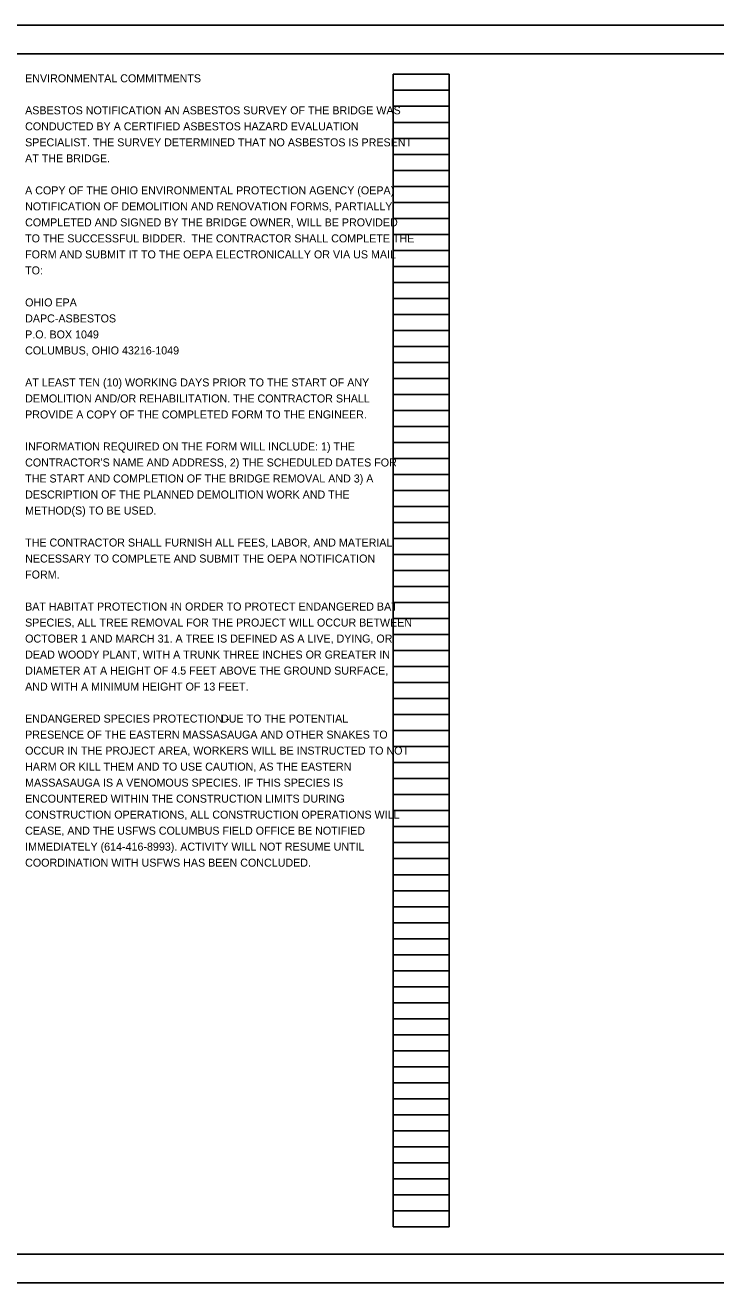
# Model space of a CAD drawing. Extents: x -8.3 to 34, y 0 to 22.
# Drawn here: x 9.82 to 21.91, y 0 to 22 of the extents above; entities that cross this region are included whole.
import ezdxf

# ---------------------------------------------------------------- set-up
doc = ezdxf.new("R2010")
doc.units = 0
for name, color, linetype in [('SH_Border', 7, 'Continuous'), ('SH_Cut_Line', 7, 'Continuous'), ('SH_Data', 7, 'Continuous'), ('SH_Text', 7, 'Continuous')]:
    doc.layers.add(name, color=color, linetype=linetype)

msp = doc.modelspace()

# ---------------------------------------------------------------- linework, layer by layer
at = {"layer": 'SH_Border'}
msp.add_lwpolyline([(1.5, 21.5), (33.5, 21.5), (33.5, 0.5), (1.5, 0.5)], close=True, dxfattribs=at)
at = {"layer": 'SH_Cut_Line'}
msp.add_lwpolyline([(0, 0), (34, 0), (34, 22), (0, 22)], close=True, dxfattribs=at)
at = {"layer": 'SH_Data'}
for p, q in [((16.26, 0.98), (16.26, 21.14)), ((16.26, 21.14), (17.24, 21.14)), ((17.24, 0.98), (17.24, 21.14)), ((16.26, 20.86), (17.24, 20.86)), ((16.26, 20.58), (17.24, 20.58)), ((16.26, 20.3), (17.24, 20.3)), ((16.26, 20.02), (17.24, 20.02)), ((16.26, 19.74), (17.24, 19.74)), ((16.26, 19.46), (17.24, 19.46)), ((16.26, 19.18), (17.24, 19.18)), ((16.26, 18.9), (17.24, 18.9)), ((16.26, 18.62), (17.24, 18.62)), ((16.26, 18.34), (17.24, 18.34)), ((16.26, 18.06), (17.24, 18.06)), ((16.26, 17.78), (17.24, 17.78)), ((16.26, 17.5), (17.24, 17.5)), ((16.26, 17.22), (17.24, 17.22)), ((16.26, 16.94), (17.24, 16.94)), ((16.26, 16.66), (17.24, 16.66)), ((16.26, 16.38), (17.24, 16.38)), ((16.26, 16.1), (17.24, 16.1)), ((16.26, 15.82), (17.24, 15.82)), ((16.26, 15.54), (17.24, 15.54)), ((16.26, 15.26), (17.24, 15.26)), ((16.26, 14.98), (17.24, 14.98)), ((16.26, 14.7), (17.24, 14.7)), ((16.26, 14.42), (17.24, 14.42)), ((16.26, 14.14), (17.24, 14.14)), ((16.26, 13.86), (17.24, 13.86)), ((16.26, 13.58), (17.24, 13.58)), ((16.26, 13.3), (17.24, 13.3)), ((16.26, 13.02), (17.24, 13.02)), ((16.26, 12.74), (17.24, 12.74)), ((16.26, 12.46), (17.24, 12.46)), ((16.26, 12.18), (17.24, 12.18)), ((16.26, 11.9), (17.24, 11.9)), ((16.26, 11.62), (17.24, 11.62)), ((16.26, 11.34), (17.24, 11.34)), ((16.26, 11.06), (17.24, 11.06)), ((16.26, 10.78), (17.24, 10.78)), ((16.26, 10.5), (17.24, 10.5)), ((16.26, 10.22), (17.24, 10.22)), ((16.26, 9.94), (17.24, 9.94)), ((16.26, 9.66), (17.24, 9.66)), ((16.26, 9.38), (17.24, 9.38)), ((16.26, 9.1), (17.24, 9.1)), ((16.26, 8.82), (17.24, 8.82)), ((16.26, 8.54), (17.24, 8.54)), ((16.26, 8.26), (17.24, 8.26)), ((16.26, 7.98), (17.24, 7.98)), ((16.26, 7.7), (17.24, 7.7)), ((16.26, 7.42), (17.24, 7.42)), ((16.26, 7.14), (17.24, 7.14)), ((16.26, 6.86), (17.24, 6.86)), ((16.26, 6.58), (17.24, 6.58)), ((16.26, 6.3), (17.24, 6.3)), ((16.26, 6.02), (17.24, 6.02)), ((16.26, 5.74), (17.24, 5.74)), ((16.26, 5.46), (17.24, 5.46)), ((16.26, 5.18), (17.24, 5.18)), ((16.26, 4.9), (17.24, 4.9)), ((16.26, 4.62), (17.24, 4.62)), ((16.26, 4.34), (17.24, 4.34)), ((16.26, 4.06), (17.24, 4.06)), ((16.26, 3.78), (17.24, 3.78)), ((16.26, 3.5), (17.24, 3.5)), ((16.26, 3.22), (17.24, 3.22)), ((16.26, 2.94), (17.24, 2.94)), ((16.26, 2.66), (17.24, 2.66)), ((16.26, 2.38), (17.24, 2.38)), ((16.26, 2.1), (17.24, 2.1)), ((16.26, 1.82), (17.24, 1.82)), ((16.26, 1.54), (17.24, 1.54)), ((16.26, 1.26), (17.24, 1.26)), ((16.26, 0.98), (17.24, 0.98))]:
    msp.add_line(p, q, dxfattribs=at)

# ---------------------------------------------------------------- texts
at = {"layer": 'SH_Text'}
for s, p in [('ENVIRONMENTAL COMMITMENTS', (9.82, 21)), ('ASBESTOS NOTIFICATION - ', (9.82, 20.44)), ('AN ASBESTOS SURVEY OF THE BRIDGE WAS ', (12.264, 20.44)), ('CONDUCTED BY A CERTIFIED ASBESTOS HAZARD EVALUATION ', (9.82, 20.16)), ('SPECIALIST. THE SURVEY DETERMINED THAT NO ASBESTOS IS PRESENT ', (9.82, 19.88)), ('AT THE BRIDGE.', (9.82, 19.6)), ('A COPY OF THE OHIO ENVIRONMENTAL PROTECTION AGENCY (OEPA) ', (9.82, 19.04)), ('NOTIFICATION OF DEMOLITION AND RENOVATION FORMS, PARTIALLY ', (9.82, 18.76)), ('COMPLETED AND SIGNED BY THE BRIDGE OWNER, WILL BE PROVIDED ', (9.82, 18.48)), ('TO THE SUCCESSFUL BIDDER.  THE CONTRACTOR SHALL COMPLETE THE ', (9.82, 18.2)), ('FORM AND SUBMIT IT TO THE OEPA ELECTRONICALLY OR VIA US MAIL ', (9.82, 17.92)), ('TO:', (9.82, 17.64)), ('OHIO EPA', (9.82, 17.08)), ('DAPC-ASBESTOS', (9.82, 16.8)), ('P.O. BOX 1049', (9.82, 16.52)), ('COLUMBUS, OHIO 43216-1049', (9.82, 16.24)), ('AT LEAST TEN (10) WORKING DAYS PRIOR TO THE START OF ANY ', (9.82, 15.68)), ('DEMOLITION AND/OR REHABILITATION. THE CONTRACTOR SHALL ', (9.82, 15.4)), ('PROVIDE A COPY OF THE COMPLETED FORM TO THE ENGINEER.', (9.82, 15.12)), ('INFORMATION REQUIRED ON THE FORM WILL INCLUDE: 1) THE ', (9.82, 14.56)), ("CONTRACTOR'S NAME AND ADDRESS, 2) THE SCHEDULED DATES FOR ", (9.82, 14.28)), ('THE START AND COMPLETION OF THE BRIDGE REMOVAL AND 3) A ', (9.82, 14)), ('DESCRIPTION OF THE PLANNED DEMOLITION WORK AND THE ', (9.82, 13.72)), ('METHOD(S) TO BE USED. ', (9.82, 13.44)), ('THE CONTRACTOR SHALL FURNISH ALL FEES, LABOR, AND MATERIAL ', (9.82, 12.88)), ('NECESSARY TO COMPLETE AND SUBMIT THE OEPA NOTIFICATION ', (9.82, 12.6)), ('FORM.', (9.82, 12.32)), ('BAT HABITAT PROTECTION - ', (9.82, 11.76)), ('IN ORDER TO PROTECT ENDANGERED BAT ', (12.379, 11.76)), ('SPECIES, ALL TREE REMOVAL FOR THE PROJECT WILL OCCUR BETWEEN ', (9.82, 11.48)), ('OCTOBER 1 AND MARCH 31. A TREE IS DEFINED AS A LIVE, DYING, OR ', (9.82, 11.2)), ('DEAD WOODY PLANT, WITH A TRUNK THREE INCHES OR GREATER IN ', (9.82, 10.92)), ('DIAMETER AT A HEIGHT OF 4.5 FEET ABOVE THE GROUND SURFACE, ', (9.82, 10.64)), ('AND WITH A MINIMUM HEIGHT OF 13 FEET.', (9.82, 10.36)), ('ENDANGERED SPECIES PROTECTION - ', (9.82, 9.8)), ('DUE TO THE POTENTIAL ', (13.249, 9.8)), ('PRESENCE OF THE EASTERN MASSASAUGA AND OTHER SNAKES TO ', (9.82, 9.52)), ('OCCUR IN THE PROJECT AREA, WORKERS WILL BE INSTRUCTED TO NOT ', (9.82, 9.24)), ('HARM OR KILL THEM AND TO USE CAUTION, AS THE EASTERN ', (9.82, 8.96)), ('MASSASAUGA IS A VENOMOUS SPECIES. IF THIS SPECIES IS ', (9.82, 8.68)), ('ENCOUNTERED WITHIN THE CONSTRUCTION LIMITS DURING ', (9.82, 8.4)), ('CONSTRUCTION OPERATIONS, ALL CONSTRUCTION OPERATIONS WILL ', (9.82, 8.12)), ('CEASE, AND THE USFWS COLUMBUS FIELD OFFICE BE NOTIFIED ', (9.82, 7.84)), ('IMMEDIATELY (614-416-8993). ACTIVITY WILL NOT RESUME UNTIL ', (9.82, 7.56)), ('COORDINATION WITH USFWS HAS BEEN CONCLUDED. ', (9.82, 7.28))]:
    msp.add_text(s, height=0.14, dxfattribs=at).set_placement(p)

doc.saveas('drawing.dxf')
